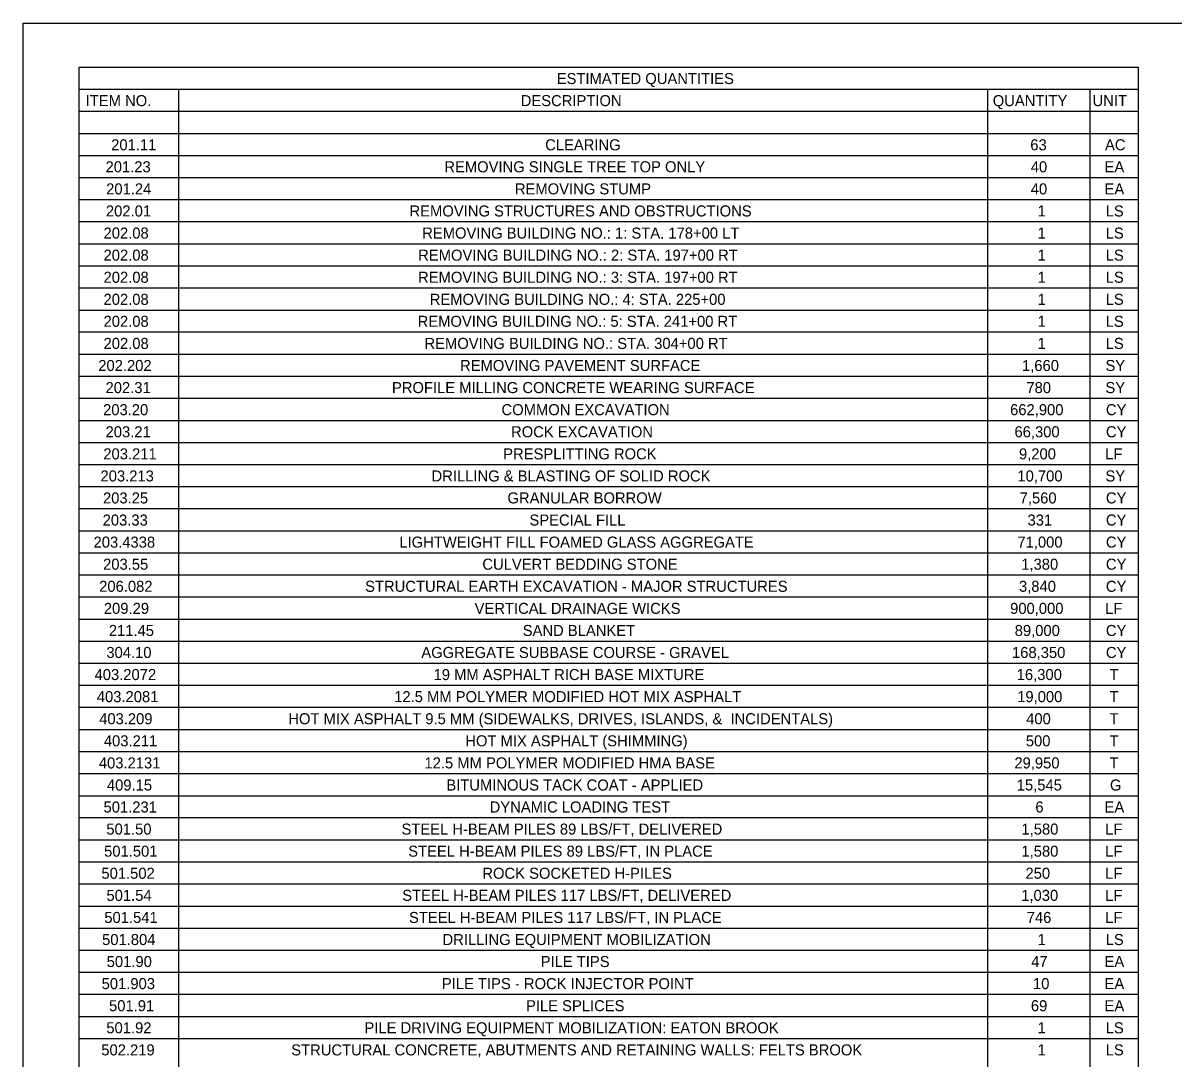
# Model space of a CAD drawing. Extents: x -18.7 to 5.6, y -2.7 to 5.1.
# Drawn here: x -17.663 to -16.637, y 3.09 to 4.014 of the extents above; entities that cross this region are included whole.
import ezdxf

# ---------------------------------------------------------------- set-up
doc = ezdxf.new("R2010")
doc.units = 0
doc.layers.add('ANNOTATION', color=7, linetype='Continuous')
doc.layers.add('BORDER', color=7, linetype='Continuous')

msp = doc.modelspace()

# ---------------------------------------------------------------- linework, layer by layer
at = {"layer": 'ANNOTATION'}
msp.add_lwpolyline([(-17.663, 4.0141), (-13.3075, 4.0141), (-13.3075, 2.1719), (-17.663, 2.1719)], close=True, dxfattribs=at)
at = {"layer": 'BORDER'}
for p, q in [((-17.613, 3.9551), (-16.6688, 3.9551)), ((-17.5245, 3.9551), (-17.5245, 2.2424)), ((-16.8032, 3.9551), (-16.8032, 2.2424)), ((-16.7118, 3.9551), (-16.7118, 2.2424)), ((-17.613, 3.9354), (-16.6688, 3.9354)), ((-17.613, 3.9157), (-16.6688, 3.9157)), ((-17.613, 3.896), (-16.6688, 3.896)), ((-17.613, 3.8764), (-16.6688, 3.8764)), ((-17.613, 3.8567), (-16.6688, 3.8567)), ((-17.613, 3.837), (-16.6688, 3.837)), ((-17.613, 3.8173), (-16.6688, 3.8173)), ((-17.613, 3.7976), (-16.6688, 3.7976)), ((-17.613, 3.7779), (-16.6688, 3.7779)), ((-17.613, 3.7582), (-16.6688, 3.7582)), ((-17.613, 3.7386), (-16.6688, 3.7386)), ((-17.613, 3.7189), (-16.6688, 3.7189)), ((-17.613, 3.6992), (-16.6688, 3.6992)), ((-17.613, 3.6795), (-16.6688, 3.6795)), ((-17.613, 3.6598), (-16.6688, 3.6598)), ((-17.613, 3.6401), (-16.6688, 3.6401)), ((-17.613, 3.6204), (-16.6688, 3.6204)), ((-17.613, 3.6008), (-16.6688, 3.6008)), ((-17.613, 3.5811), (-16.6688, 3.5811)), ((-17.613, 3.5614), (-16.6688, 3.5614)), ((-17.613, 3.5417), (-16.6688, 3.5417)), ((-17.613, 3.522), (-16.6688, 3.522)), ((-17.613, 3.5023), (-16.6688, 3.5023)), ((-17.613, 3.4826), (-16.6688, 3.4826)), ((-17.613, 3.463), (-16.6688, 3.463)), ((-17.613, 3.4433), (-16.6688, 3.4433)), ((-17.613, 3.4236), (-16.6688, 3.4236)), ((-17.613, 3.4039), (-16.6688, 3.4039)), ((-17.613, 3.3842), (-16.6688, 3.3842)), ((-17.613, 3.3645), (-16.6688, 3.3645)), ((-17.613, 3.3448), (-16.6688, 3.3448)), ((-17.613, 3.3251), (-16.6688, 3.3251)), ((-17.613, 3.3055), (-16.6688, 3.3055)), ((-17.613, 3.2858), (-16.6688, 3.2858)), ((-17.613, 3.2661), (-16.6688, 3.2661)), ((-17.613, 3.2464), (-16.6688, 3.2464)), ((-17.613, 3.2267), (-16.6688, 3.2267)), ((-17.613, 3.207), (-16.6688, 3.207)), ((-17.613, 3.1873), (-16.6688, 3.1873)), ((-17.613, 3.1677), (-16.6688, 3.1677)), ((-17.613, 3.148), (-16.6688, 3.148)), ((-17.613, 3.1283), (-16.6688, 3.1283)), ((-17.613, 3.1086), (-16.6688, 3.1086))]:
    msp.add_line(p, q, dxfattribs=at)
msp.add_lwpolyline([(-17.613, 3.9748), (-16.6688, 3.9748), (-16.6688, 2.2424), (-17.613, 2.2424)], close=True, dxfattribs=at)

# ---------------------------------------------------------------- texts
at = {"layer": 'ANNOTATION'}
for s, height, p in [('201.11', 0.00984, (-17.5844, 3.9006)), ('CLEARING', 0.00984, (-17.1975, 3.9006)), ('63', 0.00984, (-16.765, 3.9006)), ('AC', 0.00984, (-16.6984, 3.9006)), ('201.23', 0.00984, (-17.5894, 3.881)), ('REMOVING SINGLE TREE TOP ONLY', 0.009843, (-17.2874, 3.881)), ('40', 0.00984, (-16.7646, 3.881)), ('EA', 0.00984, (-16.6988, 3.881)), ('201.24', 0.00984, (-17.5889, 3.8613)), ('REMOVING STUMP', 0.009843, (-17.2245, 3.8613)), ('40', 0.00984, (-16.7646, 3.8613)), ('EA', 0.00984, (-16.6988, 3.8613)), ('202.01', 0.00984, (-17.5891, 3.8416)), ('REMOVING STRUCTURES AND OBSTRUCTIONS', 0.009843, (-17.3184, 3.8416)), ('1', 0.00984, (-16.7585, 3.8416)), ('LS', 0.00984, (-16.6978, 3.8416)), ('202.08', 0.00984, (-17.5912, 3.8219)), ('REMOVING BUILDING NO.: 1: STA. 178+00 LT', 0.009843, (-17.3071, 3.8219)), ('1', 0.00984, (-16.7585, 3.8219)), ('LS', 0.00984, (-16.6978, 3.8219)), ('202.08', 0.00984, (-17.5912, 3.8022)), ('REMOVING BUILDING NO.: 2: STA. 197+00 RT', 0.009843, (-17.3107, 3.8022)), ('1', 0.00984, (-16.7585, 3.8022)), ('LS', 0.00984, (-16.6978, 3.8022)), ('202.08', 0.00984, (-17.5912, 3.7825)), ('REMOVING BUILDING NO.: 3: STA. 197+00 RT', 0.009843, (-17.3108, 3.7825)), ('1', 0.00984, (-16.7585, 3.7825)), ('LS', 0.00984, (-16.6978, 3.7825)), ('202.08', 0.00984, (-17.5912, 3.7628)), ('REMOVING BUILDING NO.: 4: STA. 225+00', 0.009843, (-17.3004, 3.7628)), ('1', 0.00984, (-16.7585, 3.7628)), ('LS', 0.00984, (-16.6978, 3.7628)), ('202.08', 0.00984, (-17.5912, 3.7432)), ('REMOVING BUILDING NO.: 5: STA. 241+00 RT', 0.009843, (-17.3112, 3.7432)), ('1', 0.00984, (-16.7585, 3.7432)), ('LS', 0.00984, (-16.6978, 3.7432)), ('202.08', 0.00984, (-17.5912, 3.7235)), ('REMOVING BUILDING NO.: STA. 304+00 RT', 0.009843, (-17.3051, 3.7235)), ('1', 0.00984, (-16.7585, 3.7235)), ('LS', 0.00984, (-16.6978, 3.7235)), ('202.202', 0.00984, (-17.5959, 3.7038)), ('REMOVING PAVEMENT SURFACE', 0.009843, (-17.2734, 3.7038)), ('1,660', 0.00984, (-16.7724, 3.7038)), ('SY', 0.00984, (-16.698, 3.7038)), ('202.31', 0.00984, (-17.5894, 3.6841)), ('PROFILE MILLING CONCRETE WEARING SURFACE', 0.009843, (-17.3341, 3.6841)), ('780', 0.00984, (-16.7685, 3.6841)), ('SY', 0.00984, (-16.698, 3.6841)), ('203.20', 0.00984, (-17.5916, 3.6644)), ('COMMON EXCAVATION', 0.009843, (-17.2364, 3.6644)), ('662,900', 0.00984, (-16.783, 3.6644)), ('CY', 0.00984, (-16.6976, 3.6644)), ('203.21', 0.00984, (-17.5894, 3.6447)), ('ROCK EXCAVATION', 0.009843, (-17.2279, 3.6447)), ('66,300', 0.00984, (-16.7791, 3.6447)), ('CY', 0.00984, (-16.6976, 3.6447)), ('203.211', 0.00984, (-17.5914, 3.625)), ('PRESPLITTING ROCK', 0.009843, (-17.2349, 3.625)), ('9,200', 0.00984, (-16.7751, 3.625)), ('LF', 0.00984, (-16.6982, 3.625)), ('203.213', 0.00984, (-17.5939, 3.6053)), ('DRILLING & BLASTING OF SOLID ROCK       ', 0.009843, (-17.2988, 3.6053)), ('10,700', 0.00984, (-16.7765, 3.6053)), ('SY', 0.00984, (-16.698, 3.6053)), ('203.25', 0.00984, (-17.5917, 3.5857)), ('GRANULAR BORROW', 0.009843, (-17.2311, 3.5857)), ('7,560', 0.00984, (-16.7745, 3.5857)), ('CY', 0.00984, (-16.6976, 3.5857)), ('203.33', 0.00984, (-17.592, 3.566)), ('SPECIAL FILL', 0.009843, (-17.2115, 3.566)), ('331', 0.00984, (-16.7675, 3.566)), ('CY', 0.00984, (-16.6976, 3.566)), ('203.4338', 0.00984, (-17.6001, 3.5463)), ('LIGHTWEIGHT FILL FOAMED GLASS AGGREGATE', 0.009843, (-17.3275, 3.5463)), ('71,000', 0.00984, (-16.7765, 3.5463)), ('CY', 0.00984, (-16.6976, 3.5463)), ('203.55', 0.00984, (-17.5916, 3.5266)), ('CULVERT BEDDING STONE', 0.009843, (-17.2535, 3.5266)), ('1,380', 0.00984, (-16.7731, 3.5266)), ('CY', 0.00984, (-16.6976, 3.5266)), ('206.082', 0.00984, (-17.5951, 3.5069)), ('STRUCTURAL EARTH EXCAVATION - MAJOR STRUCTURES', 0.009843, (-17.358, 3.5069)), ('3,840', 0.00984, (-16.7751, 3.5069)), ('CY', 0.00984, (-16.6976, 3.5069)), ('209.29', 0.00984, (-17.5909, 3.4872)), ('VERTICAL DRAINAGE WICKS', 0.009843, (-17.2604, 3.4872)), ('900,000', 0.00984, (-16.783, 3.4872)), ('LF', 0.00984, (-16.6982, 3.4872)), ('211.45', 0.00984, (-17.5865, 3.4675)), ('SAND BLANKET', 0.009843, (-17.2175, 3.4675)), ('89,000', 0.00984, (-16.7789, 3.4675)), ('CY', 0.00984, (-16.6976, 3.4675)), ('304.10', 0.00984, (-17.5887, 3.4479)), ('AGGREGATE SUBBASE COURSE - GRAVEL', 0.009843, (-17.3079, 3.4479)), ('168,350', 0.00984, (-16.7813, 3.4479)), ('CY', 0.00984, (-16.6976, 3.4479)), ('403.2072', 0.00984, (-17.5992, 3.4282)), ('19 MM ASPHALT RICH BASE MIXTURE', 0.009843, (-17.297, 3.4282)), ('16,300', 0.00984, (-16.7771, 3.4282)), ('T', 0.00984, (-16.6943, 3.4282)), ('403.2081', 0.00984, (-17.5972, 3.4085)), ('12.5 MM POLYMER MODIFIED HOT MIX ASPHALT', 0.009843, (-17.3321, 3.4085)), ('19,000', 0.00984, (-16.7767, 3.4085)), ('T', 0.00984, (-16.6943, 3.4085)), ('403.209', 0.00984, (-17.5951, 3.3888)), ('HOT MIX ASPHALT 9.5 MM (SIDEWALKS, DRIVES, ISLANDS, &  INCIDENTALS)', 0.009843, (-17.4265, 3.3888)), ('400', 0.00984, (-16.7687, 3.3888)), ('T', 0.00984, (-16.6943, 3.3888)), ('403.211', 0.00984, (-17.5909, 3.3691)), ('HOT MIX ASPHALT (SHIMMING)', 0.009843, (-17.2687, 3.3691)), ('500', 0.00984, (-16.769, 3.3691)), ('T', 0.00984, (-16.6943, 3.3691)), ('403.2131', 0.00984, (-17.5954, 3.3494)), ('12.5 MM POLYMER MODIFIED HMA BASE', 0.009843, (-17.3051, 3.3494)), ('29,950', 0.00984, (-16.7792, 3.3494)), ('T', 0.00984, (-16.6943, 3.3494)), ('409.15', 0.00984, (-17.5882, 3.3297)), ('BITUMINOUS TACK COAT - APPLIED', 0.009843, (-17.2856, 3.3297)), ('15,545', 0.00984, (-16.7771, 3.3297)), ('G', 0.00984, (-16.694, 3.3297)), ('501.231', 0.00984, (-17.5912, 3.3101)), ('DYNAMIC LOADING TEST', 0.009843, (-17.247, 3.3101)), ('6', 0.00984, (-16.7605, 3.3101)), ('EA', 0.00984, (-16.6988, 3.3101)), ('501.50', 0.00984, (-17.5887, 3.2904)), ('STEEL H-BEAM PILES 89 LBS/FT, DELIVERED', 0.009843, (-17.3256, 3.2904)), ('1,580', 0.00984, (-16.7729, 3.2904)), ('LF', 0.00984, (-16.6982, 3.2904)), ('501.501', 0.00984, (-17.5907, 3.2707)), ('STEEL H-BEAM PILES 89 LBS/FT, IN PLACE', 0.009843, (-17.3196, 3.2707)), ('1,580', 0.00984, (-16.7729, 3.2707)), ('LF', 0.00984, (-16.6982, 3.2707)), ('501.502', 0.00984, (-17.5931, 3.251)), ('ROCK SOCKETED H-PILES', 0.009843, (-17.2535, 3.251)), ('250', 0.00984, (-16.7693, 3.251)), ('LF', 0.00984, (-16.6982, 3.251)), ('501.54', 0.00984, (-17.5886, 3.2313)), ('STEEL H-BEAM PILES 117 LBS/FT, DELIVERED', 0.009843, (-17.3249, 3.2313)), ('1,030', 0.00984, (-16.7731, 3.2313)), ('LF', 0.00984, (-16.6982, 3.2313)), ('STEEL H-BEAM PILES 117 LBS/FT, IN PLACE', 0.009843, (-17.3189, 3.2116)), ('501.541', 0.00984, (-17.5905, 3.2116)), ('746', 0.00984, (-16.7682, 3.2116)), ('LF', 0.00984, (-16.6982, 3.2116)), ('501.804', 0.00984, (-17.5925, 3.1919)), ('DRILLING EQUIPMENT MOBILIZATION', 0.009843, (-17.289, 3.1919)), ('1', 0.00984, (-16.7585, 3.1919)), ('LS', 0.00984, (-16.6978, 3.1919)), ('501.90', 0.00984, (-17.5884, 3.1723)), ('PILE TIPS', 0.00984, (-17.2015, 3.1723)), ('47', 0.00984, (-16.7642, 3.1723)), ('EA', 0.00984, (-16.6988, 3.1723)), ('501.903', 0.00984, (-17.5929, 3.1526)), ('PILE TIPS - ROCK INJECTOR POINT', 0.009843, (-17.2896, 3.1526)), ('10', 0.00984, (-16.7626, 3.1526)), ('EA', 0.00984, (-16.6988, 3.1526)), ('501.91', 0.00984, (-17.5863, 3.1329)), ('PILE SPLICES', 0.009843, (-17.2146, 3.1329)), ('69', 0.00984, (-16.7645, 3.1329)), ('EA', 0.00984, (-16.6988, 3.1329)), ('501.92', 0.00984, (-17.5887, 3.1132)), ('PILE DRIVING EQUIPMENT MOBILIZATION: EATON BROOK', 0.009843, (-17.3586, 3.1132)), ('1', 0.00984, (-16.7585, 3.1132)), ('LS', 0.00984, (-16.6978, 3.1132)), ('502.219', 0.00984, (-17.5932, 3.0935)), ('STRUCTURAL CONCRETE, ABUTMENTS AND RETAINING WALLS: FELTS BROOK', 0.009843, (-17.4239, 3.0935)), ('1', 0.00984, (-16.7585, 3.0935)), ('LS', 0.00984, (-16.6978, 3.0935))]:
    msp.add_text(s, height=height, dxfattribs=at).set_placement(p)
at = {"layer": 'BORDER'}
for s, height, p in [('ESTIMATED QUANTITIES', 0.009843, (-17.1872, 3.9597)), ('ITEM NO.', 0.00984, (-17.6071, 3.94)), ('DESCRIPTION', 0.009843, (-17.2193, 3.94)), ('QUANTITY', 0.00984, (-16.7985, 3.94)), ('UNIT', 0.00984, (-16.7095, 3.94))]:
    msp.add_text(s, height=height, dxfattribs=at).set_placement(p)

doc.saveas('drawing.dxf')
